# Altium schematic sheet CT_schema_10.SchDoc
size 278 x 170 mm
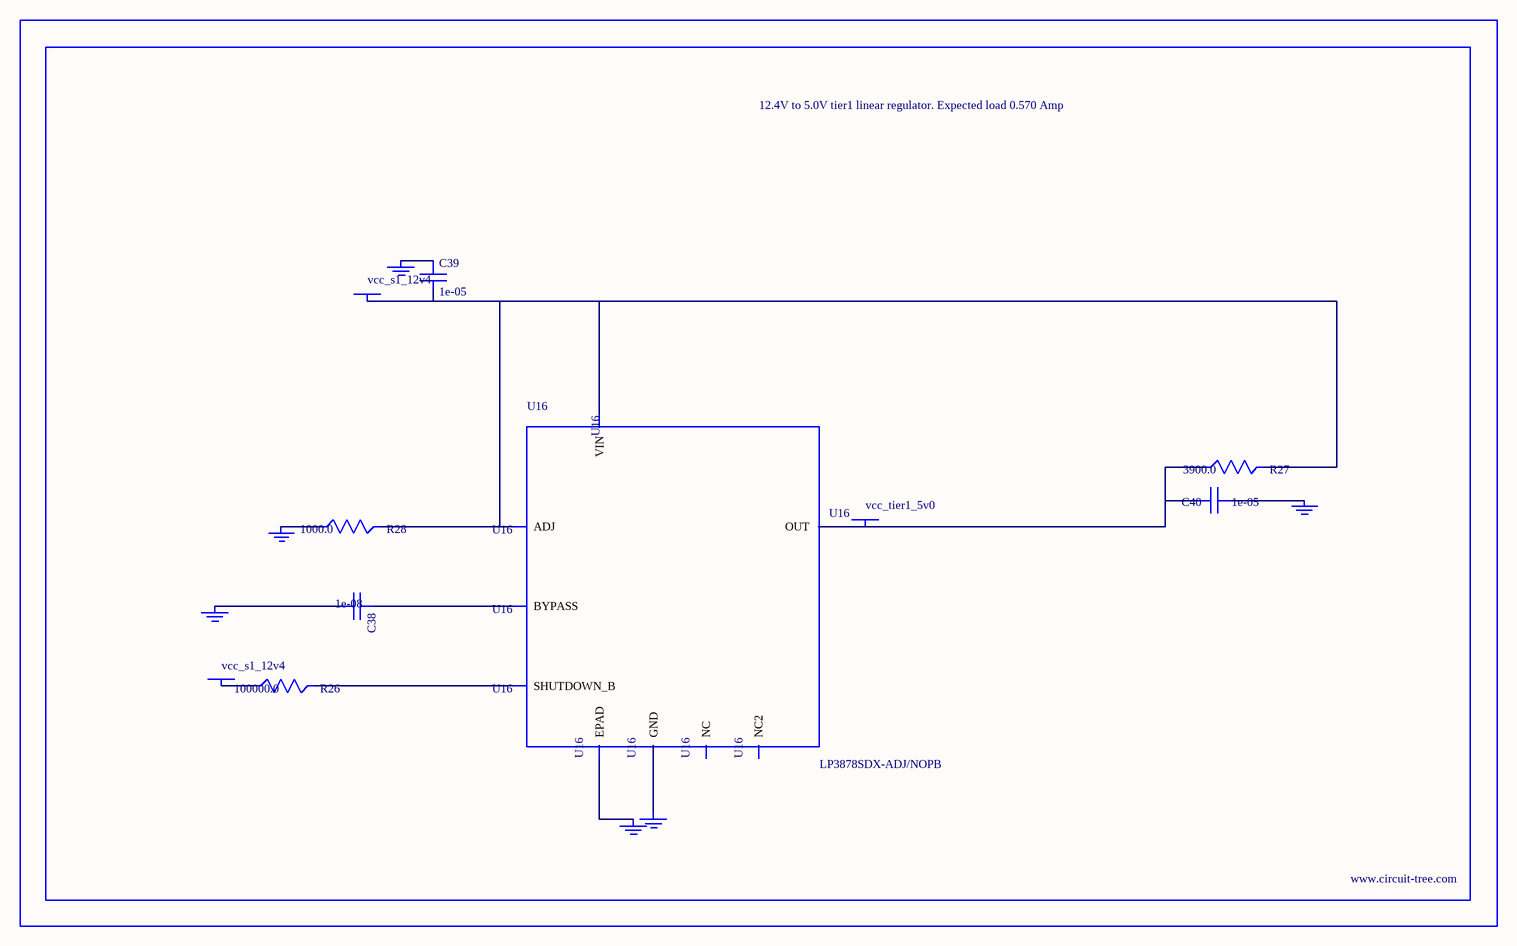
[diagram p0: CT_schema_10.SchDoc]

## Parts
BORDER9  (no value)
C38  1e-08  [C0402]
C39  1e-05  [C1210]
C40  1e-05  [C1210]
GND_INSTANCE_9_0  (no value)
GND_INSTANCE_9_1  (no value)
GND_INSTANCE_9_2  (no value)
GND_INSTANCE_9_3  (no value)
GND_INSTANCE_9_4  (no value)
GND_INSTANCE_9_5  (no value)
POWER_INSTANCE_9_0  vcc_s1_12v4
POWER_INSTANCE_9_1  vcc_s1_12v4
POWER_INSTANCE_9_2  vcc_tier1_5v0
R26  100000.0  [R0603]
R27  3900.0  [R0603]
R28  1000.0  [R0603]
U16  LP3878SDX-ADJ/NOPB  [WSON-8]

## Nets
NetC38_1: C38.1 U16.1(BYPASS)
NetC38_2: C38.2 GND_INSTANCE_9_0.0(GND)
NetC39_1: C39.1 GND_INSTANCE_9_1.0(GND)
NetC39_2: C39.2 POWER_INSTANCE_9_0.0(PWR) R27.2 R28.2 U16.4(VIN) U16.6(ADJ)
NetC40_1: C40.1 GND_INSTANCE_9_2.0(GND)
NetC40_2: C40.2 POWER_INSTANCE_9_2.0(PWR) R27.1 U16.5(OUT)
NetGND_INSTANCE_9_3_0: GND_INSTANCE_9_3.0(GND) R28.1
NetGND_INSTANCE_9_4_0: GND_INSTANCE_9_4.0(GND) U16.PAD(EPAD)
NetGND_INSTANCE_9_5_0: GND_INSTANCE_9_5.0(GND) U16.3(GND)
NetPOWER_INSTANCE_9_1_0: POWER_INSTANCE_9_1.0(PWR) R26.1
NetR26_2: R26.2 U16.8(SHUTDOWN_B)

Not connected (* = marked no-connect by the designer): U16 2(NC) 7(NC2)

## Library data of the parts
BORDER9 = BORDER_PAGE9
C38 = C0402C103K3RAC
C39 = C1210C106K5PACTU
C40 = GRM32DR61E106MA12L
GND_INSTANCE_9_0-GND_INSTANCE_9_5 = GND
POWER_INSTANCE_9_0-POWER_INSTANCE_9_2 = PWR
R26 = RC0603JR-07100KL
R27 = RC0603JR-073K9L
R28 = RC0603JR-071KL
